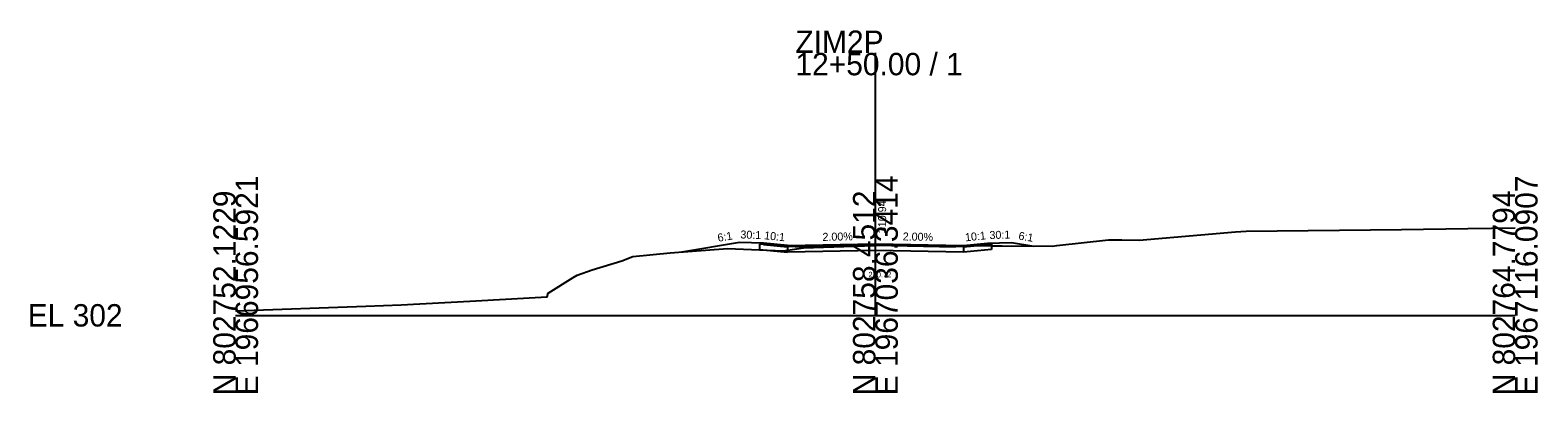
# Model space of a CAD drawing. Extents: x 1950845 to 1951408, y 736831 to 740365.
# Drawn here: x 1950844.5 to 1951033.1, y 739331.5 to 739376.9 of the extents above; entities that cross this region are included whole.
import ezdxf

# ---------------------------------------------------------------- set-up
doc = ezdxf.new("R2010")
doc.units = 0
for name, color, linetype in [('RD_GPK_XS_Cell', 7, 'Continuous'), ('RD_XS_Base', 7, 'Continuous'), ('RD_XS_EarthShd', 7, 'Continuous'), ('RD_XS_ExGround', 7, 'Continuous'), ('RD_XS_Pave', 7, 'Continuous'), ('RD_XS_PaveOvlay', 7, 'Continuous'), ('RD_XS_TieSlope', 7, 'Continuous'), ('RD_XS_TX_Elev_EX', 7, 'Continuous'), ('RD_XS_TX_Elev_PR', 7, 'Continuous'), ('RD_XS_TX_Slope', 7, 'Continuous')]:
    doc.layers.add(name, color=color, linetype=linetype)

msp = doc.modelspace()

# ---------------------------------------------------------------- linework, layer by layer
at = {"layer": 'RD_GPK_XS_Cell'}
for p, q in [((1950950.22, 739341.19), (1950950.22, 739374.01)), ((1950870.22, 739341.19), (1950950.22, 739341.19)), ((1950950.22, 739341.19), (1951030.22, 739341.19))]:
    msp.add_line(p, q, dxfattribs=at)
at = {"layer": 'RD_XS_Base'}
for points in [[(1950939.22, 739349.75), (1950936.22, 739350.05), (1950935.72, 739350.1)], [(1950935.72, 739350.1), (1950935.72, 739349.44)], [(1950939.22, 739349.75), (1950939.22, 739349.09)], [(1950940.22, 739349.77), (1950950.22, 739349.97), (1950960.22, 739349.77)], [(1950961.22, 739349.75), (1950964.22, 739350.05), (1950964.72, 739350.1)], [(1950961.22, 739349.75), (1950961.22, 739349.09)], [(1950964.72, 739350.1), (1950964.72, 739349.44)], [(1950935.72, 739349.44), (1950939.22, 739349.09)], [(1950961.22, 739349.1), (1950950.22, 739349.31), (1950939.22, 739349.09)], [(1950964.72, 739349.44), (1950961.22, 739349.09)]]:
    msp.add_lwpolyline(points, dxfattribs=at)
at = {"layer": 'RD_XS_EarthShd'}
for points in [[(1950936.22, 739350.21), (1950933.22, 739350.31)], [(1950964.22, 739350.21), (1950967.22, 739350.31)]]:
    msp.add_lwpolyline(points, dxfattribs=at)
at = {"layer": 'RD_XS_ExGround'}
msp.add_lwpolyline([(1950870.22, 739341.76), (1950886.49, 739342.35), (1950890.93, 739342.52), (1950899.5, 739342.98), (1950909.19, 739343.5), (1950909.29, 739343.95), (1950912.44, 739345.94), (1950912.91, 739346.21), (1950914.8, 739346.88), (1950918.51, 739348.02), (1950919.89, 739348.55), (1950924.56, 739349), (1950931.71, 739349.53), (1950934.72, 739349.44), (1950938.68, 739349.24), (1950940.38, 739349.51), (1950941.22, 739349.64), (1950947.52, 739349.83), (1950950.22, 739349.92), (1950953.31, 739350.03), (1950964.64, 739349.88), (1950965.34, 739349.87), (1950966.08, 739349.87), (1950972.32, 739349.82), (1950972.91, 739349.91), (1950979.39, 739350.62), (1950981.05, 739350.62), (1950983.22, 739350.58), (1950995.24, 739351.63), (1950996.59, 739351.72), (1951016.01, 739351.93), (1951024.32, 739352.06), (1951030.22, 739352.13)], dxfattribs=at)
at = {"layer": 'RD_XS_Pave'}
for points in [[(1950939.22, 739349.91), (1950936.22, 739350.21)], [(1950936.22, 739350.21), (1950936.22, 739350.05)], [(1950936.22, 739350.05), (1950939.22, 739349.75)], [(1950939.22, 739349.75), (1950939.22, 739349.91)], [(1950961.22, 739349.91), (1950964.22, 739350.21)], [(1950964.22, 739350.05), (1950961.22, 739349.75)], [(1950961.22, 739349.75), (1950961.22, 739349.91)], [(1950964.22, 739350.21), (1950964.22, 739350.05)]]:
    msp.add_lwpolyline(points, dxfattribs=at)
at = {"layer": 'RD_XS_PaveOvlay'}
for points in [[(1950939.22, 739349.91), (1950950.22, 739350.13), (1950961.22, 739349.91)], [(1950961.22, 739349.75), (1950950.22, 739349.97), (1950939.22, 739349.75)], [(1950939.22, 739349.91), (1950939.22, 739349.75)], [(1950961.22, 739349.91), (1950961.22, 739349.75)]]:
    msp.add_lwpolyline(points, dxfattribs=at)
at = {"layer": 'RD_XS_TieSlope'}
for points in [[(1950933.22, 739350.31), (1950926.01, 739349.11)], [(1950967.22, 739350.31), (1950970.05, 739349.84)]]:
    msp.add_lwpolyline(points, dxfattribs=at)

# ---------------------------------------------------------------- texts
at = {"layer": 'RD_GPK_XS_Cell'}
for s, p in [('ZIM2P', (1950940.22, 739374.01)), ('12+50.00 / 1', (1950940.22, 739371.21)), ('EL 302', (1950844.22, 739339.79))]:
    msp.add_text(s, height=2.8, dxfattribs=at).set_placement(p)
for s, p in [('E 1966956.5921', (1950873.02, 739331.19)), ('E 1967036.3414', (1950953.02, 739331.19)), ('E 1967116.0907', (1951033.02, 739331.19)), ('N 802752.1229', (1950870.22, 739331.19)), ('N 802758.4512', (1950950.22, 739331.19)), ('N 802764.7794', (1951030.22, 739331.19))]:
    msp.add_text(s, height=2.8, rotation=90, dxfattribs=at).set_placement(p)
at = {"layer": 'RD_XS_TX_Elev_EX'}
msp.add_text('220.72', height=0.7, dxfattribs=at).set_placement((1950949.35, 739345.93))
at = {"layer": 'RD_XS_TX_Elev_PR'}
msp.add_text('310.94', height=1, rotation=90, dxfattribs=at).set_placement((1950951.56, 739351.47))
at = {"layer": 'RD_XS_TX_Slope'}
for s, rotation, p in [('6:1', 9.4642, (1950930.57, 739350.38)), ('30:1', 358.0908, (1950933.33, 739350.81)), ('10:1', 354.2894, (1950936.28, 739350.71)), ('2.00%', 1.1458, (1950943.61, 739350.5)), ('2.00%', 358.8542, (1950953.63, 739350.56)), ('10:1', 5.7106, (1950961.48, 739350.44)), ('30:1', 1.9092, (1950964.5, 739350.72)), ('6:1', 350.5358, (1950968.06, 739350.68))]:
    msp.add_text(s, height=1, rotation=rotation, dxfattribs=at).set_placement(p)

doc.saveas('drawing.dxf')
